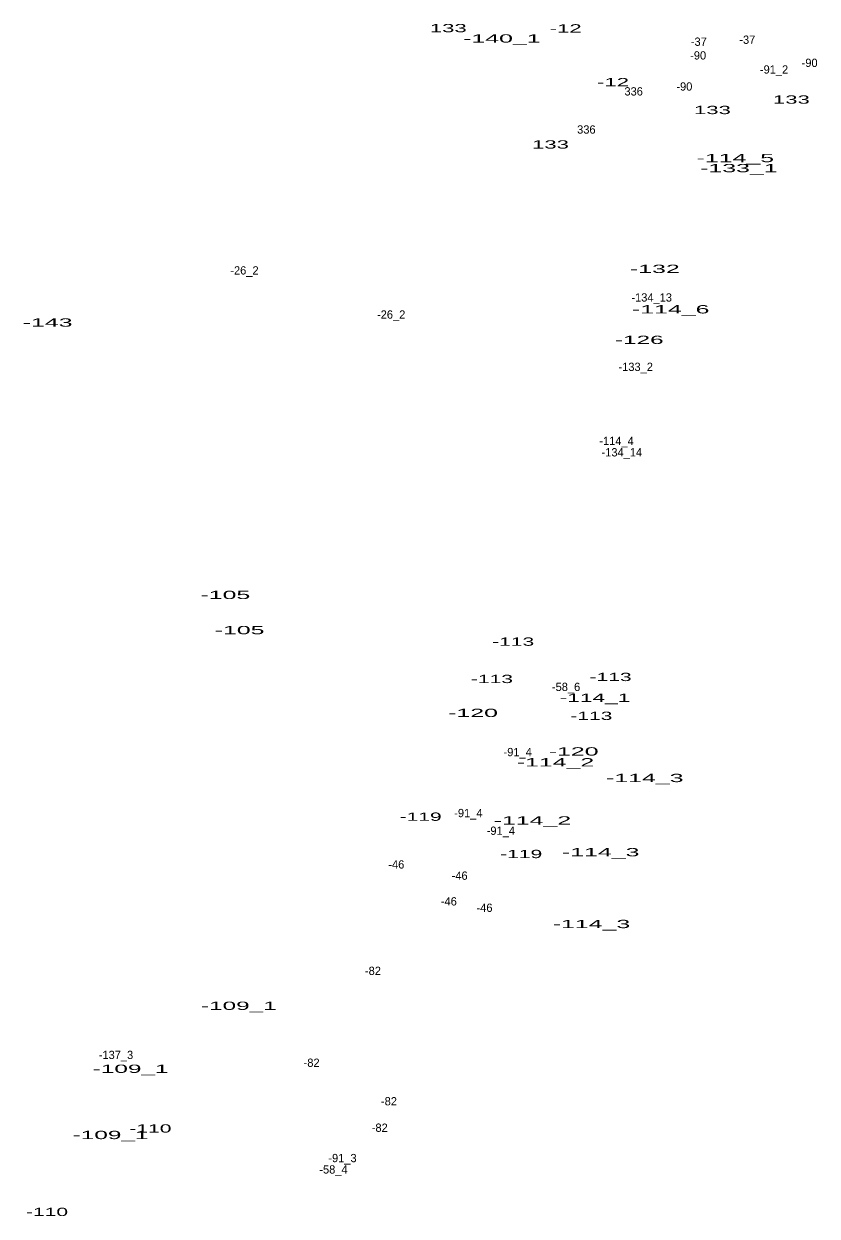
# Model space of a CAD drawing. Extents: x -662499 to -659675, y -1001682 to -998165.
# Drawn here: x -660422 to -660039, y -1001119 to -1000542 of the extents above; entities that cross this region are included whole.
import ezdxf
from ezdxf.enums import TextEntityAlignment as Align

# ---------------------------------------------------------------- set-up
doc = ezdxf.new("R2010")
doc.units = 0
doc.header["$LTSCALE"] = 1.6
doc.layers.add('24', color=7, linetype='Continuous')

msp = doc.modelspace()

# ---------------------------------------------------------------- texts
at = {"layer": '24'}
for s, width, p in [('133', 2, (-660217.127, -1000546.36)), ('-12', 2, (-660160.331, -1000546.5)), ('-140_1', 2.25, (-660191.209, -1000551.36)), ('-12', 2, (-660137.451, -1000572.49)), ('133', 2, (-660051.177, -1000580.89)), ('133', 2, (-660089.367, -1000585.93)), ('133', 2, (-660167.687, -1000602.6)), ('-114_5', 2.25, (-660078.283, -1000609.17)), ('-133_1', 2.25, (-660076.567, -1000614.04)), ('-132', 2.25, (-660117.211, -1000662.73)), ('-114_6', 2.25, (-660109.538, -1000682.28)), ('-143', 2.25, (-660410.906, -1000688.68)), ('-126', 2.2, (-660124.745, -1000697.06)), ('-105', 2.25, (-660324.937, -1000820.35)), ('-105', 2.25, (-660318.057, -1000837.37)), ('-113', 1.9, (-660185.737, -1000842.93)), ('-113', 1.9, (-660196.017, -1000860.97)), ('-113', 1.9, (-660138.627, -1000860)), ('-114_1', 2.05, (-660146.169, -1000870.06)), ('-120', 2.25, (-660205.147, -1000877.39)), ('-113', 1.9, (-660147.937, -1000878.81)), ('-120', 2.25, (-660156.487, -1000896.01)), ('-114_2', 2.25, (-660165.273, -1000901.27)), ('-114_3', 2.25, (-660122.083, -1000908.84)), ('-119', 1.9, (-660230.511, -1000927.56)), ('-114_2', 2.25, (-660176.423, -1000929.37)), ('-114_3', 2.25, (-660143.403, -1000944.72)), ('-119', 1.9, (-660181.851, -1000945.59)), ('-114_3', 2.25, (-660147.863, -1000979.43)), ('-109_1', 2.2, (-660318.429, -1001018.97)), ('-109_1', 2.2, (-660370.769, -1001049.42)), ('-109_1', 2.2, (-660380.469, -1001081.42)), ('-110', 1.9, (-660361.193, -1001078.27)), ('-110', 1.9, (-660411.203, -1001118.61))]:
    msp.add_text(s, height=4, dxfattribs=dict(at, width=width)).set_placement(p, align=Align.CENTER)
for s, p in [('-37', (-660095.951, -1000552.93)), ('-37', (-660072.491, -1000551.96)), ('-90', (-660096.264, -1000559.55)), ('-90', (-660042.364, -1000563.14)), ('-91_2', (-660059.562, -1000566.35)), ('-90', (-660102.944, -1000574.58)), ('336', (-660127.463, -1000576.94)), ('336', (-660150.343, -1000595.37)), ('-26_2', (-660315.698, -1000663.48)), ('-134_13', (-660118.753, -1000676.56)), ('-26_2', (-660244.748, -1000684.81)), ('-133_2', (-660126.476, -1000710.1)), ('-114_4', (-660135.748, -1000745.91)), ('-134_14', (-660133.187, -1000751.41)), ('-58_6', (-660160.148, -1000864.81)), ('-91_4', (-660183.556, -1000896.32)), ('-91_4', (-660207.406, -1000925.8)), ('-91_4', (-660191.706, -1000934.33)), ('-46', (-660242.255, -1000950.64)), ('-46', (-660211.625, -1000956.07)), ('-46', (-660216.865, -1000968.48)), ('-46', (-660199.605, -1000971.59)), ('-82', (-660253.565, -1001002.08)), ('-137_3', (-660377.852, -1001042.71)), ('-82', (-660283.225, -1001046.5)), ('-82', (-660245.815, -1001065.12)), ('-82', (-660250.275, -1001077.91)), ('-91_3', (-660268.302, -1001092.58)), ('-58_4', (-660272.657, -1001098.08))]:
    msp.add_text(s, height=4, dxfattribs=at).set_placement(p, align=Align.CENTER)

doc.saveas('drawing.dxf')
